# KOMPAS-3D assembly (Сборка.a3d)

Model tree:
1. Плоскость XY
2. Плоскость ZX
3. Плоскость ZY
4. Ось X
5. Ось Y
6. Ось Z
7. Начало координат

Referenced files in C:\Documents and Settings\Administrator\Desktop\Gainta Industries G1098G корпус для РЭА 135х75х50мм, пластик, серый\: Основание.m3d, Крышка.m3d
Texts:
  Линия-выноска #1
  Линия-выноска #2
  Линия-выноска #3
  Отклонения формы и база
  Марка координационной оси
  Марка/позиционное обозначение с линией-выноской
  Марка/позиционное обозначение на линии
  Марка/позиционное обозначение без линии-выноски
